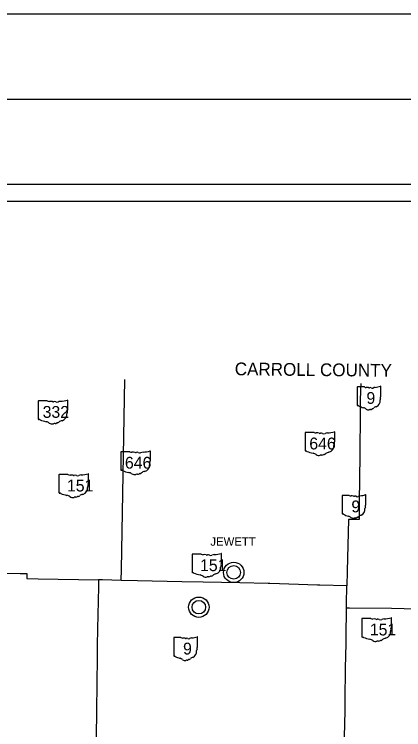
# Model space of a CAD drawing. Extents: x 0 to 70.6, y 0 to 31.9.
# Drawn here: x 5.407 to 7.699, y 17.788 to 22 of the extents above; entities that cross this region are included whole.
import ezdxf

# ---------------------------------------------------------------- set-up
doc = ezdxf.new("R2010")
doc.units = 0
for name, color, linetype in [('GM_X_Adjacent_County', 7, 'Continuous'), ('GM_X_County', 7, 'Continuous'), ('GM_X_County_Road', 7, 'Continuous'), ('GM_X_County_ROW', 7, 'Continuous'), ('GM_X_Minor_River', 7, 'Continuous'), ('GM_X_Minor_River_Text', 7, 'Continuous'), ('GM_X_Section', 7, 'Continuous'), ('GM_X_Township', 7, 'Continuous')]:
    doc.layers.add(name, color=color, linetype=linetype)

msp = doc.modelspace()

# ---------------------------------------------------------------- linework, layer by layer
at = {"layer": 'GM_X_Adjacent_County'}
for centre, radius in [((6.6982, 18.7142), 0.06), ((6.6982, 18.7142), 0.04), ((6.4929, 18.5093), 0.06), ((6.4929, 18.5093), 0.04)]:
    msp.add_circle(centre, radius, dxfattribs=at)
at = {"layer": 'GM_X_County'}
msp.add_lwpolyline([(1.5, 21.5), (33.5, 21.5), (33.5, 0.5), (1.5, 0.5)], close=True, dxfattribs=at)
at = {"layer": 'GM_X_County_ROW'}
for points in [[(7.446, 19.8259), (7.4449, 19.795), (7.4435, 19.7143), (7.4429, 19.6596), (7.4398, 19.4046), (7.437, 19.1283), (7.4363, 19.0248), (7.3744, 19.0259), (7.3668, 18.7212), (7.3647, 18.6359), (7.2047, 18.6388), (7.1907, 18.6391), (6.91, 18.6487), (6.9014, 18.6489), (6.7335, 18.6531), (6.5182, 18.6571), (6.3921, 18.6586), (6.1309, 18.6649), (6.036, 18.6667), (6.0369, 18.7317), (6.0577, 19.85)], [(5.3393, 18.7088), (5.4404, 18.7084), (5.4799, 18.7081), (5.4799, 18.6778), (5.548, 18.6768), (5.9032, 18.6702), (5.9029, 18.6556), (5.9024, 18.6289), (5.8968, 18.3826), (5.895, 18.2837), (5.8936, 18.1857), (5.8927, 18.0878), (5.8906, 17.8717), (5.8866, 17.6728)], [(6.036, 18.6667), (5.9265, 18.6697), (5.9032, 18.6702)], [(7.3616, 18.5061), (7.3619, 18.5283), (7.3647, 18.6359)], [(7.321, 16.6464), (7.3246, 16.7855), (7.3288, 17.0034), (7.3306, 17.1648), (7.3383, 17.4443), (7.3468, 17.4448), (7.3472, 17.4976), (7.3491, 17.6075), (7.3489, 17.6421), (7.3523, 17.8325), (7.3534, 17.89), (7.3544, 17.9622), (7.3569, 18.1501), (7.3595, 18.2961), (7.3593, 18.3311), (7.3616, 18.5061), (7.3799, 18.5061), (7.6271, 18.5028), (7.8521, 18.4984), (8.053, 18.4945), (8.318, 18.489), (8.6937, 18.4775)]]:
    msp.add_lwpolyline(points, dxfattribs=at)
at = {"layer": 'GM_X_Minor_River_Text'}
for p, q in [((7.4252, 19.8045), (7.4252, 19.6988)), ((7.4673, 19.8063), (7.4266, 19.8063)), ((7.5644, 19.7536), (7.5644, 19.8089)), ((5.5479, 19.7224), (5.5479, 19.6167)), ((5.6005, 19.7242), (5.5496, 19.7242)), ((5.7219, 19.6716), (5.7219, 19.7268)), ((7.5644, 19.7536), (7.5644, 19.7536)), ((5.7219, 19.6716), (5.7219, 19.6716)), ((7.1191, 19.5365), (7.1191, 19.4308)), ((7.1718, 19.5383), (7.1208, 19.5383)), ((7.2931, 19.4857), (7.2931, 19.5409)), ((7.2931, 19.4857), (7.2931, 19.4857)), ((6.0338, 19.4232), (6.0338, 19.3175)), ((6.0865, 19.425), (6.0356, 19.425)), ((6.2079, 19.3724), (6.2079, 19.4276)), ((6.2078, 19.3724), (6.2079, 19.3724)), ((5.7224, 19.2906), (5.6715, 19.2906)), ((5.8438, 19.2379), (5.8438, 19.2932)), ((5.6697, 19.2888), (5.6697, 19.1831)), ((5.8438, 19.2379), (5.8438, 19.2379)), ((7.3365, 19.166), (7.3365, 19.0603)), ((7.3787, 19.1678), (7.3379, 19.1678)), ((7.4758, 19.1152), (7.4758, 19.1704)), ((7.4757, 19.1152), (7.4758, 19.1152)), ((6.4532, 18.82), (6.4532, 18.7143)), ((6.5058, 18.8218), (6.4549, 18.8218)), ((6.6272, 18.7691), (6.6272, 18.8244)), ((6.6272, 18.7691), (6.6272, 18.7691)), ((7.4526, 18.4413), (7.4526, 18.3357)), ((7.5053, 18.4432), (7.4543, 18.4432)), ((7.6266, 18.3905), (7.6266, 18.4458)), ((7.6266, 18.3905), (7.6266, 18.3905)), ((6.3456, 18.329), (6.3456, 18.2234)), ((6.3878, 18.3308), (6.347, 18.3308)), ((6.4849, 18.2782), (6.4849, 18.3335)), ((6.4848, 18.2782), (6.4849, 18.2782))]:
    msp.add_line(p, q, dxfattribs=at)
for centre, radius, start, end in [((7.4268, 19.8047), 0.00161, 98.1301, 188.1301), ((7.477, 19.8185), 0.0156, 231.6195, 271.1119), ((7.4822, 19.7469), 0.0562, 80.4867, 94.9883), ((7.495, 19.8052), 0.00451, 219.7921, 297.1024), ((7.5016, 19.793), 0.00938, 54.4667, 119.1411), ((7.5137, 19.8098), 0.0113, 233.8562, 294.8282), ((7.5337, 19.774), 0.0297, 97.3462, 120.7689), ((7.5148, 19.9503), 0.1476, 275.8445, 288.9065), ((7.5629, 19.8091), 0.00155, 351.8621, 97.738), ((7.5231, 19.7235), 0.0369, 292.3089, 8.9858), ((7.57, 19.7305), 0.0105, 136.8065, 186.9296), ((7.5641, 19.7496), 0.0024, 107.944, 210.337), ((7.5488, 19.7426), 0.0144, 340.033, 23.6496), ((7.5628, 19.7534), 0.00166, 289.6038, 7.7341), ((7.4268, 19.6986), 0.00163, 171.9584, 258.3066), ((7.4271, 19.7094), 0.0124, 267.339, 280.6039), ((7.4296, 19.6927), 0.00448, 29.7484, 93.2717), ((7.4861, 19.7876), 0.1066, 240.4129, 257.1985), ((7.4543, 19.6513), 0.0334, 47.1842, 75.836), ((7.4904, 19.6922), 0.0212, 230.7004, 286.2918), ((7.5026, 19.6556), 0.0174, 85.6951, 111.2099), ((7.5042, 19.6843), 0.0113, 268.777, 315.5493), ((7.5144, 19.674), 0.00318, 65.7517, 132.6484), ((7.513, 19.6885), 0.0119, 282.8732, 323.2771), ((7.5387, 19.6691), 0.0202, 94.4031, 142.5768), ((7.3381, 19.1662), 0.00161, 98.1301, 188.1301), ((7.3884, 19.1801), 0.0156, 231.6195, 271.1119), ((7.3936, 19.1085), 0.0562, 80.4867, 94.9883), ((7.445, 19.1356), 0.0297, 97.3462, 120.7689), ((7.4262, 19.3119), 0.1476, 275.8445, 288.9065), ((7.4742, 19.1707), 0.00155, 351.8621, 97.738), ((7.4063, 19.1668), 0.00451, 219.7921, 297.1024), ((7.413, 19.1546), 0.00938, 54.4667, 119.1411), ((7.4251, 19.1713), 0.0113, 233.8562, 294.8282), ((7.4344, 19.085), 0.0369, 292.3089, 8.9858), ((7.4813, 19.092), 0.0105, 136.8065, 186.9296), ((7.4754, 19.1111), 0.0024, 107.944, 210.337), ((7.4601, 19.1041), 0.0144, 340.033, 23.6496), ((7.4741, 19.115), 0.00166, 289.6038, 7.7341), ((7.3381, 19.0601), 0.00163, 171.9584, 258.3066), ((7.3384, 19.0709), 0.0124, 267.339, 280.6039), ((7.3409, 19.0543), 0.00448, 29.7484, 93.2717), ((7.3975, 19.1492), 0.1066, 240.4129, 257.1985), ((7.3657, 19.0129), 0.0334, 47.1842, 75.836), ((7.4155, 19.0458), 0.0113, 268.777, 315.5493), ((7.4257, 19.0356), 0.00318, 65.7517, 132.6484), ((7.4244, 19.0501), 0.0119, 282.8732, 323.2771), ((7.45, 19.0307), 0.0202, 94.4031, 142.5768), ((7.4018, 19.0537), 0.0212, 230.7004, 286.2918), ((7.414, 19.0172), 0.0174, 85.6951, 111.2099), ((6.3472, 18.3293), 0.00161, 98.1301, 188.1301), ((6.3975, 18.3431), 0.0156, 231.6195, 271.1119), ((6.4027, 18.2715), 0.0562, 80.4867, 94.9883), ((6.4154, 18.3298), 0.00451, 219.7921, 297.1024), ((6.4221, 18.3176), 0.00938, 54.4667, 119.1411), ((6.4342, 18.3343), 0.0113, 233.8562, 294.8282), ((6.4541, 18.2986), 0.0297, 97.3462, 120.7689), ((6.4353, 18.4749), 0.1476, 275.8445, 288.9065), ((6.4833, 18.3337), 0.00155, 351.8621, 97.738), ((6.4435, 18.248), 0.0369, 292.3089, 8.9858), ((6.4904, 18.2551), 0.0105, 136.8065, 186.9296), ((6.4845, 18.2741), 0.0024, 107.944, 210.337), ((6.4692, 18.2671), 0.0144, 340.033, 23.6496), ((6.4832, 18.278), 0.00166, 289.6038, 7.7341), ((6.3473, 18.2231), 0.00163, 171.9584, 258.3066), ((6.3475, 18.2339), 0.0124, 267.339, 280.6039), ((6.35, 18.2173), 0.00448, 29.7484, 93.2717), ((6.4066, 18.3122), 0.1066, 240.4129, 257.1985), ((6.3748, 18.1759), 0.0334, 47.1842, 75.836), ((6.4109, 18.2167), 0.0212, 230.7004, 286.2918), ((6.4231, 18.1802), 0.0174, 85.6951, 111.2099), ((6.4246, 18.2088), 0.0113, 268.777, 315.5493), ((6.4348, 18.1986), 0.00318, 65.7517, 132.6484), ((6.4335, 18.2131), 0.0119, 282.8732, 323.2771), ((6.4591, 18.1937), 0.0202, 94.4031, 142.5768)]:
    msp.add_arc(centre, radius, start, end, dxfattribs=at)
for centre, major_axis, start_param, end_param in [((5.5499, 19.7226), (0.00202, 0), 1.712693, 3.28349), ((5.6127, 19.7365), (0.0196, 0), 4.042523, 4.731795), ((5.6192, 19.6649), (0.0702, 0), 1.404758, 1.657858), ((5.6351, 19.7232), (0.00564, 0), 3.836095, 5.185415), ((5.6434, 19.711), (0.0117, 0), 0.950623, 2.079405), ((5.6585, 19.7277), (0.0141, 0), 4.081561, 5.145723), ((5.6834, 19.6919), (0.0371, 0), 1.699011, 2.107814), ((5.6599, 19.8683), (0.1845, 0), 4.814394, 5.042369), ((5.72, 19.7271), (0.00194, 0), 6.141152, 7.989035), ((5.7214, 19.6675), (0.003, 0), 1.883978, 3.671073), ((5.7198, 19.6713), (0.00207, 0), 5.05454, 6.418171), ((5.6702, 19.6414), (0.0462, 0), 5.101752, 6.440018), ((5.7288, 19.6484), (0.0131, 0), 2.387724, 3.262537), ((5.7024, 19.6605), (0.018, 0), 5.934695, 6.695948), ((5.5499, 19.6165), (0.00203, 0), 3.00124, 4.508301), ((5.5502, 19.6273), (0.0155, 0), 4.665946, 4.897461), ((5.5534, 19.6106), (0.0056, 0), 0.519207, 1.627899), ((5.624, 19.7056), (0.1333, 0), 4.195997, 4.488961), ((5.5843, 19.5693), (0.0417, 0), 0.823519, 1.323587), ((5.6294, 19.6101), (0.0265, 0), 4.026481, 4.996735), ((5.6447, 19.5736), (0.0217, 0), 1.495662, 1.94098), ((5.6466, 19.6022), (0.0141, 0), 4.691044, 5.507374), ((5.6594, 19.592), (0.00397, 0), 1.147584, 2.315152), ((5.6577, 19.6065), (0.0149, 0), 4.937069, 5.64225), ((5.6897, 19.5871), (0.0253, 0), 1.647645, 2.488434), ((7.1211, 19.5367), (0.00202, 0), 1.712693, 3.28349), ((7.1839, 19.5506), (0.0196, 0), 4.042523, 4.731795), ((7.1904, 19.479), (0.0702, 0), 1.404758, 1.657858), ((7.2063, 19.5373), (0.00564, 0), 3.836095, 5.185415), ((7.2146, 19.5251), (0.0117, 0), 0.950623, 2.079405), ((7.2298, 19.5418), (0.0141, 0), 4.081561, 5.145723), ((7.2547, 19.506), (0.0371, 0), 1.699011, 2.107814), ((7.2311, 19.6824), (0.1845, 0), 4.814394, 5.042369), ((7.2912, 19.5412), (0.00194, 0), 6.141152, 7.989035), ((7.2415, 19.4555), (0.0462, 0), 5.101752, 6.440018), ((7.3001, 19.4625), (0.0131, 0), 2.387724, 3.262537), ((7.2927, 19.4816), (0.003, 0), 1.883978, 3.671073), ((7.2736, 19.4746), (0.018, 0), 5.934695, 6.695948), ((7.2911, 19.4854), (0.00207, 0), 5.05454, 6.418171), ((6.0358, 19.4234), (0.00202, 0), 1.712693, 3.28349), ((6.0987, 19.4373), (0.0196, 0), 4.042523, 4.731795), ((6.1051, 19.3657), (0.0702, 0), 1.404758, 1.657858), ((6.1211, 19.424), (0.00564, 0), 3.836095, 5.185415), ((6.1294, 19.4118), (0.0117, 0), 0.950623, 2.079405), ((6.1445, 19.4285), (0.0141, 0), 4.081561, 5.145723), ((6.1694, 19.3927), (0.0371, 0), 1.699011, 2.107814), ((6.1459, 19.5691), (0.1845, 0), 4.814394, 5.042369), ((6.2059, 19.4279), (0.00194, 0), 6.141152, 7.989035), ((7.1211, 19.4306), (0.00203, 0), 3.00124, 4.508301), ((7.1214, 19.4414), (0.0155, 0), 4.665946, 4.897461), ((7.1246, 19.4247), (0.0056, 0), 0.519207, 1.627899), ((7.1953, 19.5197), (0.1333, 0), 4.195997, 4.488961), ((7.2609, 19.4012), (0.0253, 0), 1.647645, 2.488434), ((7.1555, 19.3834), (0.0417, 0), 0.823519, 1.323587), ((7.2006, 19.4242), (0.0265, 0), 4.026481, 4.996735), ((7.2159, 19.3877), (0.0217, 0), 1.495662, 1.94098), ((7.2178, 19.4163), (0.0141, 0), 4.691044, 5.507374), ((7.2306, 19.4061), (0.00397, 0), 1.147584, 2.315152), ((7.2289, 19.4206), (0.0149, 0), 4.937069, 5.64225), ((6.1562, 19.3422), (0.0462, 0), 5.101752, 6.440018), ((6.2148, 19.3492), (0.0131, 0), 2.387724, 3.262537), ((6.2074, 19.3683), (0.003, 0), 1.883978, 3.671073), ((6.1883, 19.3613), (0.018, 0), 5.934695, 6.695948), ((6.2058, 19.3721), (0.00207, 0), 5.05454, 6.418171), ((5.6717, 19.289), (0.00202, 0), 1.712693, 3.28349), ((5.7346, 19.3029), (0.0196, 0), 4.042523, 4.731795), ((5.7818, 19.4346), (0.1845, 0), 4.814394, 5.042369), ((5.8418, 19.2934), (0.00194, 0), 6.141152, 7.989035), ((6.0359, 19.3173), (0.00203, 0), 3.00124, 4.508301), ((6.0362, 19.3281), (0.0155, 0), 4.665946, 4.897461), ((6.0393, 19.3114), (0.0056, 0), 0.519207, 1.627899), ((6.11, 19.4064), (0.1333, 0), 4.195997, 4.488961), ((6.0703, 19.2701), (0.0417, 0), 0.823519, 1.323587), ((6.1154, 19.3109), (0.0265, 0), 4.026481, 4.996735), ((6.1307, 19.2744), (0.0217, 0), 1.495662, 1.94098), ((6.1326, 19.303), (0.0141, 0), 4.691044, 5.507374), ((6.1453, 19.2928), (0.00397, 0), 1.147584, 2.315152), ((6.1436, 19.3073), (0.0149, 0), 4.937069, 5.64225), ((6.1757, 19.2879), (0.0253, 0), 1.647645, 2.488434), ((5.741, 19.2313), (0.0702, 0), 1.404758, 1.657858), ((5.757, 19.2895), (0.00564, 0), 3.836095, 5.185415), ((5.7653, 19.2773), (0.0117, 0), 0.950623, 2.079405), ((5.7804, 19.2941), (0.0141, 0), 4.081561, 5.145723), ((5.8053, 19.2583), (0.0371, 0), 1.699011, 2.107814), ((5.7921, 19.2078), (0.0462, 0), 5.101752, 6.440018), ((5.8507, 19.2148), (0.0131, 0), 2.387724, 3.262537), ((5.8433, 19.2339), (0.003, 0), 1.883978, 3.671073), ((5.8242, 19.2269), (0.018, 0), 5.934695, 6.695948), ((5.8417, 19.2377), (0.00207, 0), 5.05454, 6.418171), ((5.6718, 19.1829), (0.00203, 0), 3.00124, 4.508301), ((5.6721, 19.1937), (0.0155, 0), 4.665946, 4.897461), ((5.6752, 19.177), (0.0056, 0), 0.519207, 1.627899), ((5.7459, 19.2719), (0.1333, 0), 4.195997, 4.488961), ((5.7062, 19.1356), (0.0417, 0), 0.823519, 1.323587), ((5.7795, 19.1729), (0.0149, 0), 4.937069, 5.64225), ((5.8116, 19.1534), (0.0253, 0), 1.647645, 2.488434), ((5.7513, 19.1765), (0.0265, 0), 4.026481, 4.996735), ((5.7666, 19.14), (0.0217, 0), 1.495662, 1.94098), ((5.7685, 19.1686), (0.0141, 0), 4.691044, 5.507374), ((5.7812, 19.1583), (0.00397, 0), 1.147584, 2.315152), ((6.4552, 18.8202), (0.00202, 0), 1.712693, 3.28349), ((6.518, 18.834), (0.0196, 0), 4.042523, 4.731795), ((6.5245, 18.7625), (0.0702, 0), 1.404758, 1.657858), ((6.5404, 18.8207), (0.00564, 0), 3.836095, 5.185415), ((6.5487, 18.8085), (0.0117, 0), 0.950623, 2.079405), ((6.5638, 18.8253), (0.0141, 0), 4.081561, 5.145723), ((6.5887, 18.7895), (0.0371, 0), 1.699011, 2.107814), ((6.5652, 18.9658), (0.1845, 0), 4.814394, 5.042369), ((6.6253, 18.8246), (0.00194, 0), 6.141152, 7.989035), ((6.5755, 18.739), (0.0462, 0), 5.101752, 6.440018), ((6.6341, 18.746), (0.0131, 0), 2.387724, 3.262537), ((6.6267, 18.7651), (0.003, 0), 1.883978, 3.671073), ((6.6077, 18.7581), (0.018, 0), 5.934695, 6.695948), ((6.6251, 18.7689), (0.00207, 0), 5.05454, 6.418171), ((6.4552, 18.7141), (0.00203, 0), 3.00124, 4.508301), ((6.4555, 18.7249), (0.0155, 0), 4.665946, 4.897461), ((6.4587, 18.7082), (0.0056, 0), 0.519207, 1.627899), ((6.5293, 18.8031), (0.1333, 0), 4.195997, 4.488961), ((6.595, 18.6846), (0.0253, 0), 1.647645, 2.488434), ((6.4896, 18.6668), (0.0417, 0), 0.823519, 1.323587), ((6.5347, 18.7077), (0.0265, 0), 4.026481, 4.996735), ((6.55, 18.6711), (0.0217, 0), 1.495662, 1.94098), ((6.5519, 18.6998), (0.0141, 0), 4.691044, 5.507374), ((6.5647, 18.6895), (0.00397, 0), 1.147584, 2.315152), ((6.563, 18.704), (0.0149, 0), 4.937069, 5.64225), ((7.4546, 18.4416), (0.00202, 0), 1.712693, 3.28349), ((7.5174, 18.4554), (0.0196, 0), 4.042523, 4.731795), ((7.5239, 18.3838), (0.0702, 0), 1.404758, 1.657858), ((7.5399, 18.4421), (0.00564, 0), 3.836095, 5.185415), ((7.5481, 18.4299), (0.0117, 0), 0.950623, 2.079405), ((7.5633, 18.4466), (0.0141, 0), 4.081561, 5.145723), ((7.5882, 18.4109), (0.0371, 0), 1.699011, 2.107814), ((7.5647, 18.5872), (0.1845, 0), 4.814394, 5.042369), ((7.6247, 18.446), (0.00194, 0), 6.141152, 7.989035), ((7.575, 18.3603), (0.0462, 0), 5.101752, 6.440018), ((7.6336, 18.3674), (0.0131, 0), 2.387724, 3.262537), ((7.6262, 18.3864), (0.003, 0), 1.883978, 3.671073), ((7.6071, 18.3795), (0.018, 0), 5.934695, 6.695948), ((7.6246, 18.3903), (0.00207, 0), 5.05454, 6.418171), ((7.4546, 18.3354), (0.00203, 0), 3.00124, 4.508301), ((7.4549, 18.3462), (0.0155, 0), 4.665946, 4.897461), ((7.4581, 18.3296), (0.0056, 0), 0.519207, 1.627899), ((7.5288, 18.4245), (0.1333, 0), 4.195997, 4.488961), ((7.5945, 18.306), (0.0253, 0), 1.647645, 2.488434), ((7.489, 18.2882), (0.0417, 0), 0.823519, 1.323587), ((7.5341, 18.3291), (0.0265, 0), 4.026481, 4.996735), ((7.5494, 18.2925), (0.0217, 0), 1.495662, 1.94098), ((7.5514, 18.3211), (0.0141, 0), 4.691044, 5.507374), ((7.5641, 18.3109), (0.00397, 0), 1.147584, 2.315152), ((7.5624, 18.3254), (0.0149, 0), 4.937069, 5.64225)]:
    msp.add_ellipse(centre, major_axis=major_axis, ratio=0.8, start_param=start_param, end_param=end_param, dxfattribs=at)
at = {"layer": 'GM_X_Section'}
msp.add_lwpolyline([(0, 0), (34, 0), (34, 22), (0, 22)], close=True, dxfattribs=at)
at = {"layer": 'GM_X_Township'}
for p, q in [((2, 21), (9, 21)), ((2.1, 20.9), (8.9, 20.9))]:
    msp.add_line(p, q, dxfattribs=at)

# ---------------------------------------------------------------- texts
at = {"layer": 'GM_X_County_Road'}
msp.add_text('JEWETT', height=0.05, rotation=0, dxfattribs=at).set_placement((6.5606, 18.871))
at = {"layer": 'GM_X_Minor_River'}
msp.add_text('CARROLL COUNTY', height=0.075, rotation=359.4336, dxfattribs=at).set_placement((6.7041, 19.8751))
at = {"layer": 'GM_X_Minor_River_Text'}
for s, height, p in [('9', 0.0696, (7.4796, 19.7062)), ('332', 0.06961, (5.5736, 19.6242)), ('646', 0.06961, (7.1432, 19.4383)), ('646', 0.06961, (6.0579, 19.325)), ('151', 0.06961, (5.7167, 19.1906)), ('9', 0.0696, (7.3909, 19.0678)), ('151', 0.06961, (6.5001, 18.7217)), ('151', 0.06961, (7.4996, 18.3431)), ('9', 0.0696, (6.4, 18.2308))]:
    msp.add_text(s, height=height, dxfattribs=at).set_placement(p)

doc.saveas('drawing.dxf')
